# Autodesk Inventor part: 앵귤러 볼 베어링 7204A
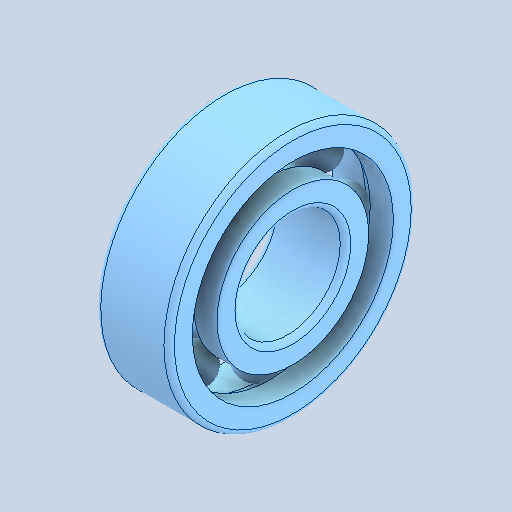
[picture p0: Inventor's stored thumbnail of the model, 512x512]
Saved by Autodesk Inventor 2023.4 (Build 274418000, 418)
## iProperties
Created: 2024-11
Part Number: 앵귤러 볼 베어링 7204A
Material: 강철, 연강
Description: 앵귤러 콘택트 볼 베어링
Document SubType Name: Modeling
Designer: EDU
Density: 7.85 g/cm^3
Appearance: 기본값
Author: jhkim
Sending System: Autodesk Inventor 2025
Preprocessor: ST-DEVELOPER v20
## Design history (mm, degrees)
feature "Solid1"
feature "Solid1:1"
feature "Solid1:2"
feature "Solid1:3"
feature "Solid1:4"
feature "Solid1:5"
feature "Solid1:6"
feature "Solid1:7"
feature "Solid1:8"
feature "Solid1:9"
node "솔리드1"
node "솔리드2"
node "솔리드3"
node "솔리드4"
node "솔리드5"
node "솔리드6"
node "솔리드7"
node "솔리드8"
node "솔리드9"
node "솔리드10"
